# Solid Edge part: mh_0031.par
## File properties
Title: holder_handle_b
Author: edge
Template: normal.par
Last saved by: edge
Revision: 33
Application: Solid Edge
Material: ＡＢＳ
非切断部品: False
文書内容のタイプ: 0
Density: 0.001200 g/mm^3
Accuracy: 0.99
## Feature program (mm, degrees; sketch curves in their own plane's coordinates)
sketch for "unnamed Protrusion 1" plane through (0, 0, 0) normal (0, 0, 1) x-axis (1, 0, 0)
  line (-45, 0) -> (45, 0)
  line (45, 0) -> (45, -120)
  line (45, -120) -> (-45, -120)
  line (-45, -120) -> (-45, 0)
extrude "unnamed Protrusion 1" add finite 9 along -normal
thinwall "Thinwall_1"  Thickness = 1 mm
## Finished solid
Body 1: solid body, 11 faces, 24 edges, 16 vertices.
  Faces by surface: plane 11
  Edges by curve: line 24
Bounding box of the edges (mm): 90.000 x 120.000 x 9.000, from (-45, -120, -9) to (45, 0, 0).
Planar faces by outward normal: +x 2, +y 2, +z 2, -x 2, -y 2, -z 1
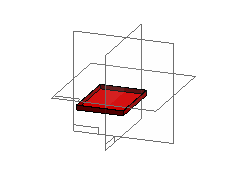
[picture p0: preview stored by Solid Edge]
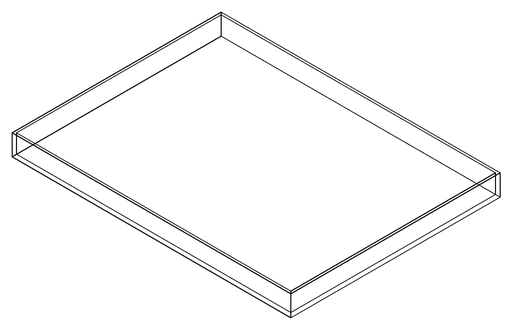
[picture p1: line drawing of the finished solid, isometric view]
